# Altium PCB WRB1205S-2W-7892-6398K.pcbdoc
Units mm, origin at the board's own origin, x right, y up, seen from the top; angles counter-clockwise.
Board outline 21.35 x 12 mm, 2 copper layers (Top Layer, Bottom Layer), stack 0.78 mm thick; 24 components, 16 nets, 64 pads, 20 vias.
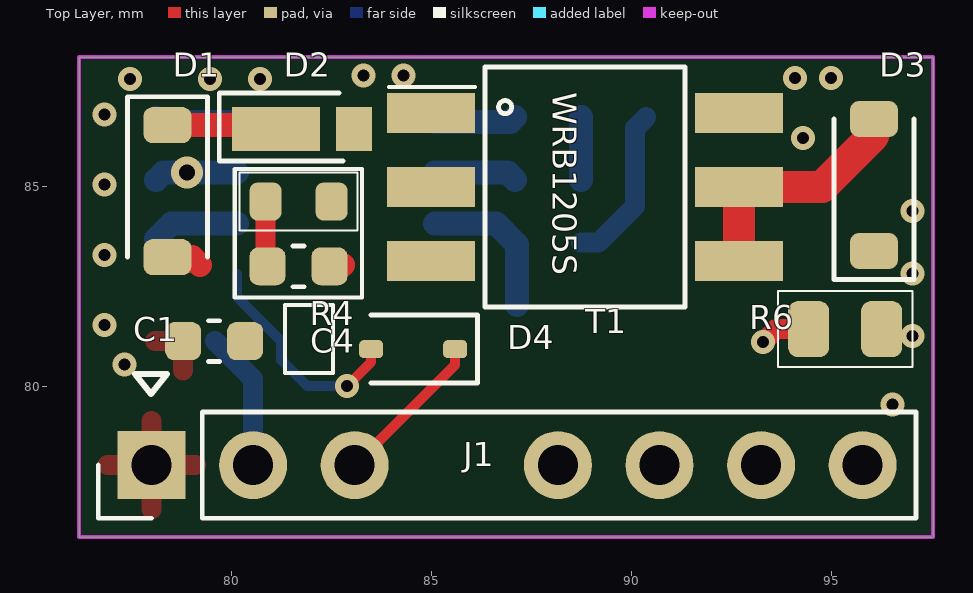
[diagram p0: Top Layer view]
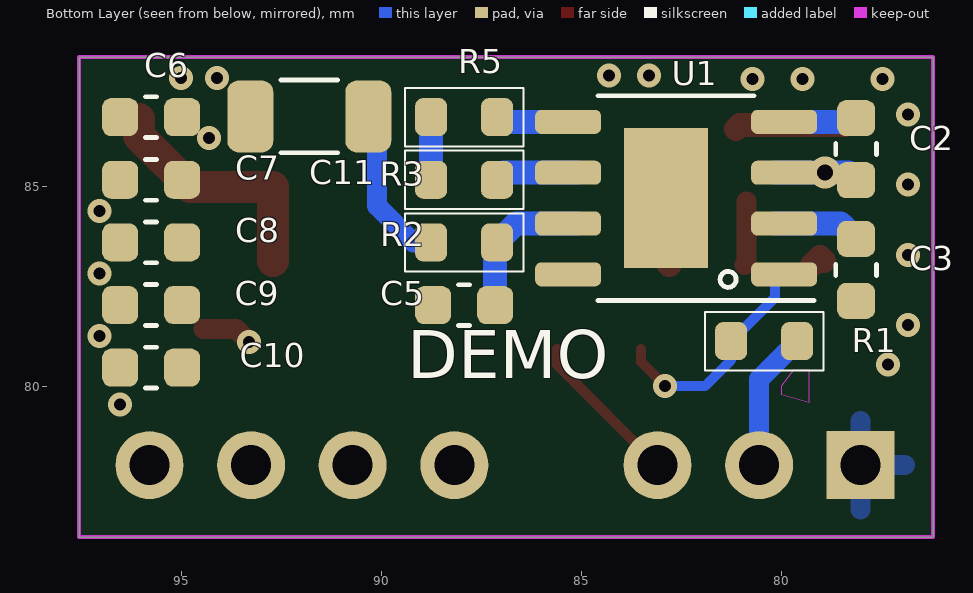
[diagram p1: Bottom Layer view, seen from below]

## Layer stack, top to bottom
Top Solder Mask Layer: solder mask 0.01, Dk 3.3
Top Layer: signal copper 0.035
Dielectric2: surface 0.71, FR4, Dk 4.5
Bottom Layer: signal copper 0.035
Bottom Solder Mask Layer: solder mask 0.01, Dk 3.3

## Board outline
76.2,88.222 97.55,88.222 97.55,76.222 76.2,76.222

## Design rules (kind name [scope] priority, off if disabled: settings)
BoardOutlineClearance copperThickness1oz [All] p0: genericclearance=0.254 ignorepadtopadclearanceinfootprint=FALSE except(0: Arc-SplitContinuation Track-SplitContinuation SMDPad-SplitContinuation THPad-SplitContinuation Via-SplitContinuation Fill-SplitContinuation Poly-SplitContinuation Region-SplitContinuation Text-SplitContinuation)
BoardOutlineClearance safeClearance1 [All] p0: genericclearance=0.254 ignorepadtopadclearanceinfootprint=FALSE except(0: Arc-SplitContinuation Track-SplitContinuation SMDPad-SplitContinuation THPad-SplitContinuation Via-SplitContinuation Fill-SplitContinuation Poly-SplitContinuation Region-SplitContinuation Text-SplitContinuation)
BoardOutlineClearance otherClearance [All] p0: genericclearance=0.254 ignorepadtopadclearanceinfootprint=FALSE except(0: Arc-SplitContinuation Track-SplitContinuation SMDPad-SplitContinuation THPad-SplitContinuation Via-SplitContinuation Fill-SplitContinuation Poly-SplitContinuation Region-SplitContinuation Text-SplitContinuation)
Clearance copperThickness1oz [All] p1: gap=0.178 ignorepadtopadclearanceinfootprint=FALSE
Clearance safeClearance1 [All] p1: gap=0.178 ignorepadtopadclearanceinfootprint=FALSE
Clearance otherClearance [All] p1: gap=0.178 ignorepadtopadclearanceinfootprint=FALSE
DiffPairsRouting differentialPair [All] p1: maxuncoupledlength=10 minlimit=5 maxlimit=Infinity mostfreqgap=6 toplayer_minwidth=5 toplayer_prefwidth=100 toplayer_maxwidth=100 bottomlayer_minwidth=5 bottomlayer_prefwidth=100 bottomlayer_maxwidth=100
PasteMaskExpansion pasteMaskExpansion [All] p1: expansion=0
PlaneConnect innerPlane [All] p1: planeconnectstyle=Relief reliefexpansion=0.508 reliefentries=4 reliefconductorwidth=0.254 reliefairgap=0.254
PolygonConnect copper0 [All] p1: connectstyle=Direct reliefentries=4 reliefconductorwidth=10 polygonreliefangle="90 Angle" airgapwidth=10
PolygonConnect copper1 [All] p1: connectstyle=Relief reliefentries=4 reliefconductorwidth=19.685 polygonreliefangle="90 Angle" airgapwidth=10
RoutingVias viaSize [All] p1: viastyle="Through Hole" holewidth=24 minholewidth=11.811 maxholewidth=393.7 width=24 minwidth=11.811 maxwidth=393.7
SolderMaskExpansion solderMaskExpansion [All] p1: useseparateexpansions=TRUE expansion=2 expansionbottom=2
Width copperThickness1oz [All] p1: maxlimit=100 minlimit=5 preferedwidth=10

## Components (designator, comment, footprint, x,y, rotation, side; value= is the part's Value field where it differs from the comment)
C1 "10uF" C0603 79.575,81.122 r0 top
C2 "1uF" C0603 78.125,85.922 r270 bottom
C3 "1uF" C0603 78.125,82.902 r90 bottom
C4 "470pF" C0603 81.685,82.993 r0 top
C5 "10pF" C0603 87.925,82.022 r180 bottom
C6 "22uF" C0603 95.75,86.722 r0 bottom
C7 "22uF" C0603 95.75,85.156 r0 bottom
C8 "22uF" C0603 95.75,83.591 r0 bottom
C9 "22uF" C0603 95.75,82.025 r0 bottom
C10 "22uF" C0603 95.75,80.46 r0 bottom
C11 "1nF" C1206 91.795,86.74 r180 bottom
D1 "MM1W24" SOD-123_L2.8-W1.8-LS3.9-FD 78.41,84.872 r270 top
D2 "LMBR1100ET1G" SOD-323HE_L1.9-W1.3-LS2.5-RD 82.102,86.422 r0 top
D3 "DSK24" SOD-123_L2.8-W1.8-LS3.7-RD 96.072,85.025 r90 top
D4 "B0540WS" SOD-323_L1.8-W1.3-LS2.5-RD 84.55,80.922 r180 top
J1 "Coileasy_Conn_01x07_1" coileasy:PinHeader_01x07_1_P2.54mm_Vertical 78.01,78.022 r90 top
R1 "100kΩ" R0603 80.425,81.122 r0 bottom
R2 "10kΩ" R0603 87.925,83.589 r0 bottom
R3 "100kΩ" R0603 87.925,85.155 r180 bottom
R4 "2.2kΩ" R0603 81.685,84.612 r180 top
R5 "5.6kΩ" R0603 87.925,86.722 r0 bottom
R6 "470Ω" R0805 95.35,81.422 r0 top
T1 "CMB6398K" XFMR-SMD_CMB6398K 88.85,84.972 r0 top
U1 "" coileasy:ESOP-8 82.625,84.697 r0 bottom

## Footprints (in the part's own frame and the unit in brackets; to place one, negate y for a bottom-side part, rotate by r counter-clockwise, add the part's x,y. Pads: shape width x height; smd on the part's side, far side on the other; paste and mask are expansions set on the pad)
C0603 [mm]
  rrect50% 0.9x0.95 smd: 1(-0.775,0) 2(0.775,0)
  silkscreen extent -0.14,-0.51 0.14,0.51
C1206 [mm]
  rrect50% 1.15x1.8 smd: 1(-1.475,0) 2(1.475,0)
  silkscreen extent -0.71,-0.91 0.71,0.91
coileasy:ESOP-8 [mm]
  rrect50% 1.65x0.6 smd: 1(-2.7,1.905) 2(-2.7,0.635) 3(-2.7,-0.635) 4(-2.7,-1.905) 5(2.7,-1.905) 6(2.7,-0.635) 7(2.7,0.635) 8(2.7,1.905)
  rect 2.1x3.5 smd: 9(0.25,0)
  silkscreen extent -3.45,-2.56 1.95,2.56
coileasy:PinHeader_01x07_1_P2.54mm_Vertical [mm]
  rect 1.7x1.7 hole 1: 1(0,0)
  round 1.7 hole 1: 2(0,-2.54) 3(0,-5.08) 5(0,-10.16) 6(0,-12.7) 7(0,-15.24) 8(0,-17.78)
  silkscreen extent -1.33,-19.11 1.33,1.33
R0603 [mm]
  rrect50% 0.8x0.95 smd: 1(-0.825,0) 2(0.825,0)
  silkscreen extent -1.48,-0.73 1.48,0.73
R0805 [mm]
  rrect48% 1.025x1.4 smd: 1(-0.913,0) 2(0.913,0)
  silkscreen extent -1.68,-0.95 1.68,0.95
SOD-123_L2.8-W1.8-LS3.7-RD [mm]
  rrect50% 0.9x1.2 smd: 1(-1.65,0) 2(1.65,0)
  silkscreen extent -2.36,-1 1.65,1
SOD-123_L2.8-W1.8-LS3.9-FD [mm]
  rrect50% 0.9x1.2 smd: 1(-1.65,0) 2(1.65,0)
  silkscreen extent -2.36,-1 1.65,1
SOD-323_L1.8-W1.3-LS2.5-RD [mm]
  rrect50% 0.6x0.45 smd: 1(-1.05,0) 2(1.05,0)
  silkscreen extent -1.61,-0.85 1.05,0.85
SOD-323HE_L1.9-W1.3-LS2.5-RD [mm]
  rect 2.2x1.1 smd: 1(-0.975,0)
  rect 0.9x1.1 smd: 2(0.975,0)
  silkscreen extent -2.4,-0.8 0.7,0.9
XFMR-SMD_CMB6398K [mm]
  rect 2.2x1 smd: 1(-3.85,1.85) 2(-3.85,0) 3(-3.85,-1.85) 4(3.85,-1.85) 5(3.85,0) 6(3.85,1.85)
  silkscreen extent -4.9,-3 2.5,3

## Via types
v1: diameter 0.6, hole 0.3, Top Layer to Bottom Layer, 19 vias
v2: diameter 0.8, hole 0.4, Top Layer to Bottom Layer, 1 vias

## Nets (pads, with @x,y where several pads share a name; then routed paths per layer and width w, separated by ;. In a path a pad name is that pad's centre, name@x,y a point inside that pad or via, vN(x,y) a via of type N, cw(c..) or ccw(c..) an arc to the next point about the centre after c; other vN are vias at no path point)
$1N6: J1.5
$1N8: J1.8
$1N11: D3.2 T1.4 T1.5 | length 6.2
  Top Layer w0.8: T1.4 T1.5 94.772,84.972 96.05,86.25 D3.2@96.05,86.672
$1N14: R3.1 R5.2 | length 1.6
  Bottom Layer w0.6: R3.1 R5.2
$1N15: C4.1 R4.2 | length 1.6
  Top Layer w0.5: R4.2 80.86,83.072 C4.1@80.91,83.022
$1N16: D1.1 D2.1 | length 2.8
  Top Layer w0.6: D1.1 81.027,86.522 D2.1
$1N22: C3.2 U1.2 | length 2.2
  Bottom Layer w0.6: C3.2 78.51,84.062 U1.2@80.15,84.062
CTRL: D4.1 J1.3 | length 3.9
  Top Layer w0.254: J1.3 85.6,80.532 D4.1
EN: D4.2 R1.2 U1.1 | length 5.7
  Top Layer w0.254: v1(82.9,80) 83.5,80.6 D4.2
  Bottom Layer w0.254: U1.1@80.15,82.792 80.15,82.222 R1.2 81.25,80.65 81.9,80 v1(82.9,80)
GND1: C1.1 C2.1 C3.1 C5.1 C11.2 J1.1 R2.2 U1.4 U1.9 | length 6.1
  Bottom Layer w0.5: R2.2 89.189,83.589 90.1,84.5 90.1,86.447 C11.2@90.375,86.722
  Bottom Layer w0.6: C2.1 78.22,86.602 U1.4@80.15,86.602
  other v1: 77.33,80.54 76.83,81.52 76.83,83.277 76.83,85.033 76.83,86.79 77.47,87.68 79.47,87.68 80.72,87.68
GND2: C6.1 C7.1 C8.1 C9.1 C10.1 C11.1 J1.7 R6.1 T1.6 | length 1.3
  Top Layer w0.5: v1(93.3,81.1) 93.622,81.422 R6.1
  other v1: 94.3,86.2 94.1,87.7 95,87.7
RFB: R3.2 U1.6 | length 2.1
  Bottom Layer w0.6: U1.6@85.1,85.332 86.923,85.332 R3.2
RREF: C5.2 R2.1 U1.7 | length 3.8
  Bottom Layer w0.6: U1.7@85.1,84.062 86.627,84.062 R2.1 87.15,83.539 C5.2
SW: D2.2 R4.1 R5.1 T1.1 U1.5 | length 2
  Bottom Layer w0.6: U1.5@85.1,86.602 86.98,86.602 R5.1
  other v1: 83.308,87.767 84.308,87.767
VIN: C1.2 C2.2 C4.2 D1.2 J1.2 R1.1 T1.2 T1.3 U1.3 | length 6
  Top Layer w0.6: D1.2@78.925,83.122 79.025,83.222 79.225,83.022 ; C4.2@82.79,83.022 C4.2@82.8,83.022
  Bottom Layer w0.5: R1.1 80.55,80.172 J1.2
  Bottom Layer w0.6: C2.2 78.31,85.332 v2(78.9,85.332) U1.3@80.15,85.332
VO: C6.2 C7.2 C8.2 C9.2 C10.2 D3.1 J1.6 R6.2
  other v1: 96.53,79.54 97.04,81.25 97.04,82.81 97.04,84.38
pads on no net: U1.8

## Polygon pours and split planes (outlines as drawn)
SW on Top Layer (solid, remove dead copper, pour order 14): 86.325,86.222 83.325,86.222 83.325,84.122 82.125,84.122 82.125,88.092 86.325,88.092
VO on Top Layer (solid, remove dead copper, pour order 2): 95.6,85.23 97.5,85.23 97.5,79.1 92.034,79.1 91.7,78.7 91.7,76.2 89.9,76.2 89.9,78.8 91.2,80.4 95.6,80.4
VIN on Top Layer (solid, remove dead copper, pour order 10): 79.7,76.2 79.7,81.4 79,81.9 77.81,81.9 77.81,85.8 79.7,85.8 79.7,82.7 80.2,82.3 82.1,82.3 82.1,83.8 83.9,83.8 83.9,85.5 86.1,85.5 86.1,81.4 83,81.4 81.6,80.1 81.6,76.2
VO on Bottom Layer (solid, remove dead copper, pour order 14): 97.5,87.2 97.5,79.1 95.75,79.1 95.75,87.2
GND1 on Bottom Layer (solid, remove dead copper, pour order 26): 76.2,79.7 76.2,88.2 83.9,88.2 83.9,82.5 86.5,82.5 86.5,81.4 88.1,81.4 88.1,84.2 89.4,84.2 89.4,80.6 81.9,80.6 79.3,79.7
GND1 on Bottom Layer (solid, remove dead copper, pour order 30): 76.2,76.2 76.2,80.4 79.3,80.4 79.3,76.2
SW on Bottom Layer (solid, remove dead copper, pour order 22): 87.025,88.092 87.025,86.322 82.625,86.322 82.625,88.092
GND1 on Top Layer (solid, remove dead copper, pour order 18): 76.2,76.2 76.2,88.2 81.3,88.2 81.3,76.2
GND2 on Top Layer (solid, remove dead copper, pour order 8): 91.6,85.7 91.6,88.2 95.4,88.2 95.4,85.7
GND2 on Bottom Layer (solid, remove dead copper, pour order 16): 92.8,88.2 95.4,88.2 95.4,76.2 92.8,76.2

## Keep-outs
Bottom Layer:
  region: 79.3,79.6 79.3,80.4 79.7,80.4 80,80 80,79.8
Board Outline Layer:
  the board outline again, w0.1

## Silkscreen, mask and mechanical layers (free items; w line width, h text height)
Top Silkscreen Layer:
  lines w0.102: 80.09,82.21 83.27,82.21 83.27,85.43 80.09,85.43 80.09,82.21 ; 81.35,80.322 82.55,80.322 82.55,82.022 81.35,82.022 81.35,80.322
  lines w0.15: 77.6,80.3 78.4,80.3 78,79.8 77.6,80.3
  text "WRB1205S" at 88.04,87.35 h0.6 r270
Bottom Silkscreen Layer:
  text "DEMO" at 89.341,80.199 h1.2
